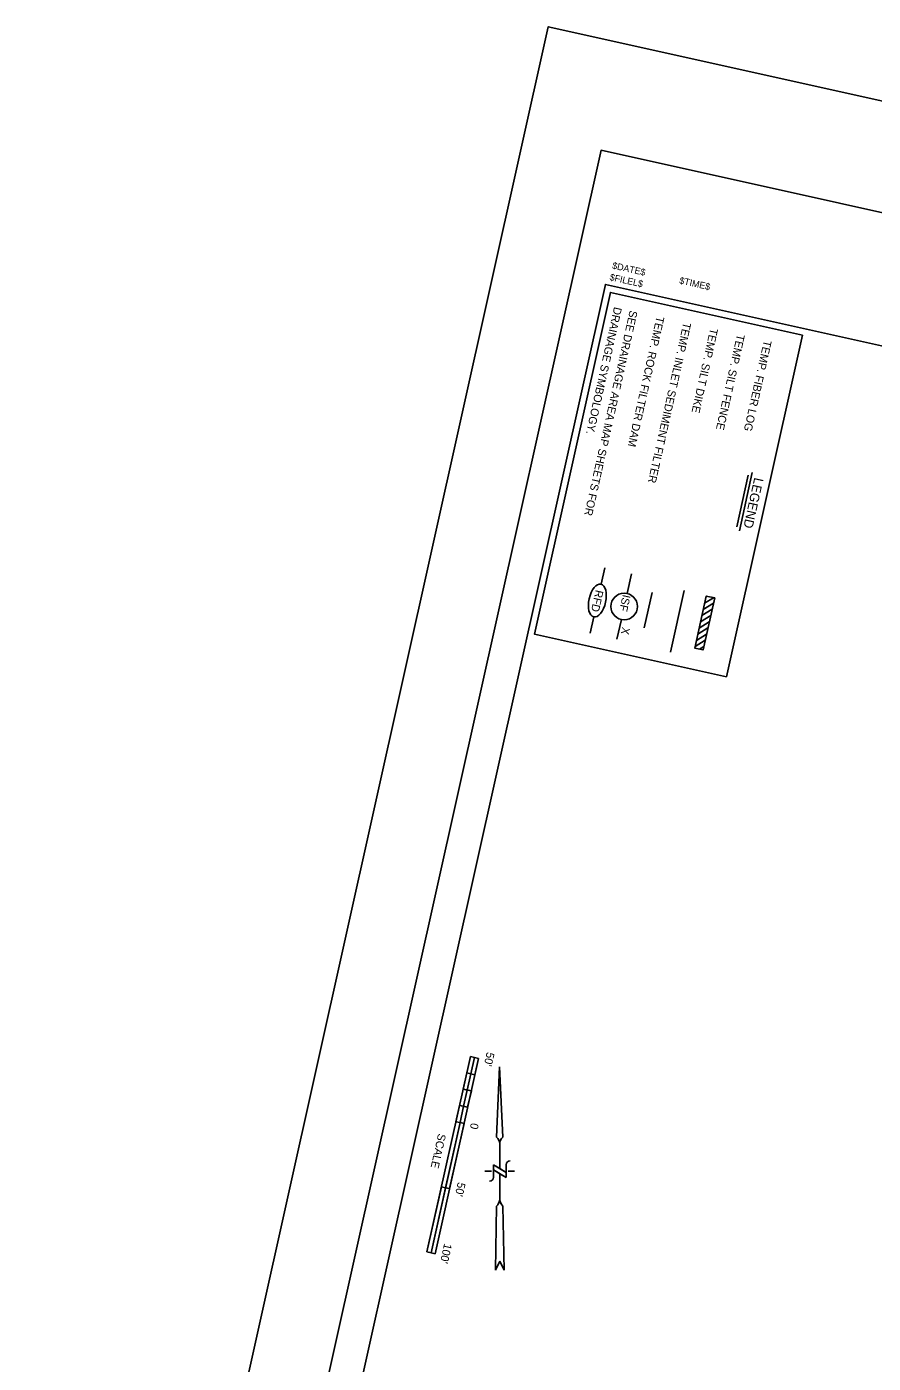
# Model space of a CAD drawing. Extents: x 2149822 to 2151384, y 143435 to 145586.
# Drawn here: x 2149822 to 2150456, y 144584 to 145586 of the extents above; entities that cross this region are included whole.
import ezdxf

# ---------------------------------------------------------------- set-up
doc = ezdxf.new("R2010")
doc.units = 0
for name, color, linetype in [('PR_Erosion_Control', 7, 'Continuous'), ('PR_Erosion_Control_Fiber_Log', 7, 'Continuous'), ('PR_Erosion_Control_Silt_Dike', 7, 'Continuous'), ('PR_Erosion_Control_Silt_Fence', 7, 'Continuous'), ('PR_Erosion_Control_Txt', 7, 'Continuous'), ('PR_Storm_Txt', 7, 'Continuous'), ('SHT_North_Arrow', 7, 'Continuous'), ('SHT_Plot_Shape_Full', 7, 'Continuous'), ('SHT_Plot_Shape_Half', 7, 'Continuous'), ('SHT_Plot_Stamp', 7, 'Continuous'), ('SHT_Scale', 7, 'Continuous'), ('SHT_Sheet_Border', 7, 'Continuous')]:
    doc.layers.add(name, color=color, linetype=linetype)

msp = doc.modelspace()

# ---------------------------------------------------------------- linework, layer by layer
at = {"layer": 'PR_Erosion_Control'}
for p, q in [((2150252.3, 145168), (2150255, 145180.3)), ((2150244.1, 145131.1), (2150246.8, 145143.4)), ((2150267.5, 145141.5), (2150264.2, 145126.7))]:
    msp.add_line(p, q, dxfattribs=at)
msp.add_lwpolyline([(2150403.2, 145354.7), (2150346.2, 145098.5), (2150202.3, 145130.5), (2150259.3, 145386.7)], close=True, dxfattribs=at)
for points in [[(2150362.6, 145249.7), (2150354, 145210.9)], [(2150365.6, 145251.6), (2150355.9, 145208)], [(2150275.1, 145175.8), (2150271.8, 145161)]]:
    msp.add_lwpolyline(points, dxfattribs=at)
msp.add_circle((2150269.6, 145151.2), 10, dxfattribs=at)
msp.add_ellipse((2150249.5, 145155.7), major_axis=(-2.7, -12.3), ratio=0.500861, dxfattribs=at)
at = {"layer": 'PR_Erosion_Control_Fiber_Log'}
for p, q in [((2150336.6, 145157.8), (2150329.9, 145153.7)), ((2150331.8, 145158.9), (2150331, 145158.3)), ((2150335.5, 145149.1), (2150327.9, 145144.4)), ((2150336.6, 145153.8), (2150328.9, 145149)), ((2150333.4, 145139.8), (2150325.8, 145135)), ((2150334.5, 145144.5), (2150326.8, 145139.7)), ((2150331.4, 145130.5), (2150323.7, 145125.8)), ((2150332.4, 145135.2), (2150324.8, 145130.4)), ((2150330.4, 145125.9), (2150322.7, 145121.1)), ((2150329.3, 145121.2), (2150326.1, 145119.2)), ((2150328.8, 145118.9), (2150328.4, 145118.7))]:
    msp.add_line(p, q, dxfattribs=at)
msp.add_lwpolyline([(2150337.4, 145157.6), (2150328.7, 145118.6), (2150322.5, 145120), (2150331.1, 145159)], close=True, dxfattribs=at)
at = {"layer": 'PR_Erosion_Control_Silt_Dike'}
msp.add_line((2150284.7, 145135.1), (2150290.6, 145161.7), dxfattribs=at)
at = {"layer": 'PR_Erosion_Control_Silt_Fence'}
msp.add_line((2150314.6, 145163.1), (2150304.4, 145116.9), dxfattribs=at)
at = {"layer": 'SHT_North_Arrow'}
for p, q in [((2150174, 144753.2), (2150176.3, 144806.1)), ((2150176.3, 144806.1), (2150174, 144753.2)), ((2150176.3, 144806.1), (2150178.8, 144753.2)), ((2150178.8, 144753.2), (2150176.3, 144806.1)), ((2150176.4, 144729.8), (2150176.4, 144748.5)), ((2150170.1, 144727.9), (2150165.3, 144727.8)), ((2150181.2, 144726.9), (2150171.6, 144732.6)), ((2150171.6, 144732.6), (2150181.2, 144726.9)), ((2150171.6, 144732.6), (2150171.6, 144723.1)), ((2150176.4, 144729.8), (2150171.6, 144732.6)), ((2150171.6, 144732.6), (2150171.6, 144728.8)), ((2150181.2, 144723.1), (2150171.6, 144728.8)), ((2150181.2, 144726.9), (2150176.4, 144729.8)), ((2150181.2, 144732.7), (2150181.2, 144723.1)), ((2150181.2, 144723.1), (2150181.2, 144726.9)), ((2150187.4, 144727.9), (2150182.6, 144727.9)), ((2150176.4, 144706.3), (2150176.4, 144725.9)), ((2150173.1, 144653.5), (2150174, 144701.5)), ((2150174, 144701.5), (2150173.1, 144653.5)), ((2150179.8, 144653.5), (2150178.8, 144701.5)), ((2150179.8, 144653.5), (2150178.8, 144701.5)), ((2150173.1, 144653.5), (2150176.4, 144660.2)), ((2150173.1, 144653.5), (2150176.4, 144660.2)), ((2150176.4, 144660.2), (2150179.8, 144653.5)), ((2150176.4, 144660.2), (2150179.8, 144653.5))]:
    msp.add_line(p, q, dxfattribs=at)
for points in [[(2150171.6, 144728.8), (2150176.4, 144725.9), (2150181.2, 144723.1)], [(2150176.4, 144706.3), (2150176.4, 144706.3), (2150176.4, 144706.3)]]:
    msp.add_lwpolyline(points, dxfattribs=at)
for centre, radius, start, end in [((2150170.6, 144748.5), 5.76, 0.0232, 54.4034), ((2150170.6, 144748.5), 5.76, 0.0232, 54.4034), ((2150182.1, 144748.5), 5.76, 125.6431, 180.0232), ((2150182.1, 144748.5), 5.76, 125.6431, 180.0232), ((2150184.1, 144732.7), 2.88, 90.0232, 180.0232), ((2150168.7, 144723.1), 2.88, 270.0232, 0.0232), ((2150168, 144707.4), 8.43, 314.9799, 352.4421), ((2150184.7, 144707.4), 8.43, 187.6043, 225.0665), ((2150168, 144707.4), 8.43, 314.9799, 352.0822), ((2150184.7, 144707.4), 8.43, 187.9642, 225.0665)]:
    msp.add_arc(centre, radius, start, end, dxfattribs=at)
at = {"layer": 'SHT_Plot_Shape_Full'}
msp.add_lwpolyline([(2151384.1, 145325.5), (2150993.4, 143568.4), (2149822, 143828.9), (2150212.7, 145586)], close=True, dxfattribs=at)
at = {"layer": 'SHT_Plot_Shape_Half'}
msp.add_lwpolyline([(2151326, 145254.5), (2150957, 143595.1), (2149883.3, 143833.8), (2150252.3, 145493.3)], close=True, dxfattribs=at)
at = {"layer": 'SHT_Scale'}
for p, q in [((2150154.4, 144813.7), (2150121.8, 144667.2)), ((2150160.5, 144812.3), (2150127.9, 144665.9)), ((2150160.5, 144812.3), (2150154.4, 144813.7)), ((2150157.4, 144813), (2150154.7, 144800.8)), ((2150157.4, 144813), (2150154.7, 144800.8)), ((2150160.5, 144812.3), (2150157.4, 144813)), ((2150157.8, 144800.1), (2150160.5, 144812.3)), ((2150151.7, 144801.5), (2150149, 144789.2)), ((2150157.8, 144800.1), (2150151.7, 144801.5)), ((2150154.7, 144800.8), (2150151.7, 144801.5)), ((2150154.7, 144800.8), (2150152, 144788.6)), ((2150152, 144788.6), (2150154.7, 144800.8)), ((2150154.7, 144800.8), (2150157.8, 144800.1)), ((2150155.1, 144787.9), (2150149, 144789.2)), ((2150155.1, 144787.9), (2150149, 144789.2)), ((2150149, 144789.2), (2150152, 144788.6)), ((2150152, 144788.6), (2150149.3, 144776.4)), ((2150152, 144788.6), (2150149.3, 144776.4)), ((2150155.1, 144787.9), (2150152, 144788.6)), ((2150152.3, 144775.7), (2150155.1, 144787.9)), ((2150146.2, 144777), (2150143.5, 144764.8)), ((2150152.3, 144775.7), (2150146.2, 144777)), ((2150149.3, 144776.4), (2150146.2, 144777)), ((2150149.3, 144776.4), (2150146.6, 144764.2)), ((2150146.6, 144764.2), (2150149.3, 144776.4)), ((2150149.3, 144776.4), (2150152.3, 144775.7)), ((2150146.6, 144764.2), (2150124.9, 144666.6)), ((2150146.6, 144764.2), (2150135.7, 144715.4)), ((2150138.8, 144714.7), (2150149.6, 144763.5)), ((2150143.5, 144764.8), (2150146.6, 144764.2)), ((2150143.5, 144764.8), (2150146.6, 144764.2)), ((2150146.6, 144764.2), (2150149.6, 144763.5)), ((2150149.6, 144763.5), (2150146.6, 144764.2)), ((2150132.7, 144716), (2150121.8, 144667.2)), ((2150124.9, 144666.6), (2150135.7, 144715.4)), ((2150132.7, 144716), (2150135.7, 144715.4)), ((2150135.7, 144715.4), (2150132.7, 144716)), ((2150135.7, 144715.4), (2150138.8, 144714.7)), ((2150135.7, 144715.4), (2150138.8, 144714.7)), ((2150124.9, 144666.6), (2150121.8, 144667.2)), ((2150121.8, 144667.2), (2150124.9, 144666.6)), ((2150127.9, 144665.9), (2150124.9, 144666.6))]:
    msp.add_line(p, q, dxfattribs=at)
at = {"layer": 'SHT_Sheet_Border'}
msp.add_lwpolyline([(2149913.6, 143855.3), (2150255.5, 145392.7), (2151280.5, 145164.8), (2150938.6, 143627.3)], close=True, dxfattribs=at)

# ---------------------------------------------------------------- texts
at = {"layer": 'PR_Erosion_Control_Txt'}
for s, height, p in [('TEMP. ROCK FILTER DAM', 6, (2150293.9, 145369.1)), ('TEMP. INLET SEDIMENT FILTER', 6, (2150314, 145364.6)), ('TEMP. SILT DIKE', 6, (2150334.1, 145360.2)), ('TEMP. SILT FENCE', 6, (2150354.2, 145355.7)), ('TEMP. FIBER LOG', 6, (2150374.3, 145351.2)), ('LEGEND', 7, (2150367.2, 145248.3)), ('RFD', 6, (2150248.3, 145164)), ('ISF', 6, (2150268.6, 145160.5)), ('X', 6, (2150268.2, 145136.1))]:
    msp.add_text(s, height=height, rotation=257.4638, dxfattribs=at).set_placement(p)
at = {"layer": 'PR_Storm_Txt'}
for s, p in [('SEE DRAINAGE AREA MAP SHEETS FOR', (2150273.8, 145373.6)), ('DRAINAGE SYMBOLOGY.', (2150262.1, 145376.2))]:
    msp.add_text(s, height=6, rotation=257.4638, dxfattribs=at).set_placement(p)
at = {"layer": 'SHT_Plot_Stamp'}
for s, p in [('$DATE$', (2150260.3, 145404.7)), ('$FILEL$', (2150258.4, 145396)), ('$TIME$', (2150310.6, 145393.5))]:
    msp.add_text(s, height=5, rotation=347.4638, dxfattribs=at).set_placement(p)
at = {"layer": 'SHT_Scale'}
for s, p in [("50'", (2150166.7, 144817.4)), ('0', (2150154.9, 144764.3)), ('SCALE', (2150130.3, 144756.3)), ("50'", (2150145, 144719.8)), ("100'", (2150134.8, 144673.9))]:
    msp.add_text(s, height=6, rotation=257.4638, dxfattribs=at).set_placement(p)

doc.saveas('drawing.dxf')
